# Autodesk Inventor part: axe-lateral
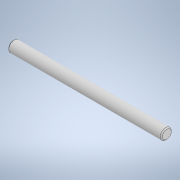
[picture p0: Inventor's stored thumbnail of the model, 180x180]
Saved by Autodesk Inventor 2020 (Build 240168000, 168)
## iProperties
Created: 2023-10
Part Number: axe-lateral
Material: Générique
Document SubType Name: Modeling
Designer: bruno
Density: 1 g/cm^3
Appearance: Par défaut
Author: bruno
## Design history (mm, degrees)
sketch "Esquisse1"
  geometry: C1 r 2.5 at (0, 0); 1 further point
  constraints: 1 centre point, 1 coincident
  dimensions: "d0" = 5 diameter of C1
extrude "Extrusion1" new body sketch "Esquisse1" distance "d1" = 70; taper "d2" = 0 deg
chamfer "Chanfrein1" distance "d3" = 0.5; stored, may be unused: second distance "d4" = 2, angle "d5" = 45 deg
node "Solide1"
